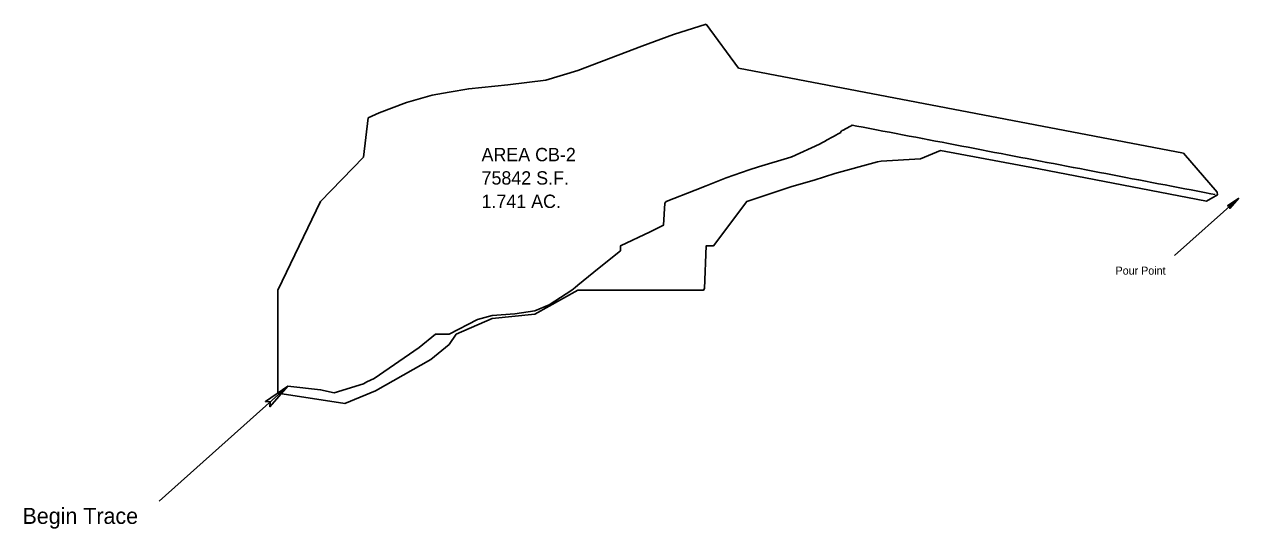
# Model space of a CAD drawing. Extents: x 2048 to 2957, y 2919 to 3297.
import ezdxf

# ---------------------------------------------------------------- set-up
doc = ezdxf.new("R2010")
doc.units = 0
for name, color, linetype in [('Default', 7, 'Continuous'), ('DESIGN - SCRATCH - User 1', 7, 'Continuous'), ('SURVEY - CENTERLINE - Preliminary', 7, 'Continuous'), ('SURVEY - CENTERLINE - Preliminary Text', 7, 'Continuous'), ('SURVEY - DRAINAGE - Area Shapes', 7, 'Continuous')]:
    doc.layers.add(name, color=color, linetype=linetype)

msp = doc.modelspace()

# ---------------------------------------------------------------- linework, layer by layer
at = {"layer": 'DESIGN - SCRATCH - User 1'}
msp.add_line((2957.46, 3167.04), (2909.3, 3124.03), dxfattribs=at)
msp.add_lwpolyline([(2957.46, 3167.04), (2950.79, 3159.41), (2950.93, 3161.21), (2949.09, 3161.31)], close=True, dxfattribs=at)
msp.add_lwpolyline([(2957.46, 3167.04), (2950.79, 3159.41), (2950.93, 3161.21), (2949.09, 3161.31), (2957.46, 3167.04)], dxfattribs=at)
at = {"layer": 'SURVEY - CENTERLINE - Preliminary'}
msp.add_lwpolyline([(2245.41, 3026.11), (2270.08, 3023.51), (2280.28, 3021.33), (2302.16, 3027.91), (2304.59, 3029.37), (2310.25, 3031.88), (2343.85, 3055.13), (2356.11, 3065.07), (2366.31, 3065.07), (2387.56, 3076.27), (2398.39, 3079.13), (2415.55, 3080.5), (2430.47, 3082.64), (2441.22, 3087.13), (2458.22, 3098.26), (2460.61, 3100.25), (2462.54, 3101.8), (2478.58, 3114.85), (2494.62, 3127.7), (2494.62, 3131.44), (2516.69, 3141.79), (2526.7, 3146.81), (2527.9, 3163.39), (2528.85, 3164.63), (2550.54, 3173.15), (2558.77, 3176.37), (2573.78, 3182.29), (2590.85, 3188.26), (2597.81, 3190.62), (2622.2, 3197.82), (2622.7, 3198.04), (2622.71, 3198.05), (2622.84, 3198.11), (2622.91, 3198.14), (2622.93, 3198.15), (2622.97, 3198.17), (2643.58, 3207.65), (2644.49, 3208.07), (2644.64, 3208.13), (2644.9, 3208.27), (2645.24, 3208.44), (2645.87, 3208.77), (2647.37, 3209.61), (2649.3, 3210.68), (2653.05, 3212.79), (2655.01, 3213.88), (2655.37, 3214.08), (2658.03, 3215.55), (2659.55, 3216.35), (2659.55, 3216.35), (2659.55, 3216.35), (2659.59, 3216.51), (2659.78, 3217.29), (2659.95, 3217.38), (2660.64, 3217.74), (2661.2, 3218.03), (2666.3, 3220.7), (2666.91, 3221.02), (2667.61, 3221.39), (2667.89, 3221.7), (2667.99, 3221.82), (2667.99, 3221.82), (2667.99, 3221.82), (2671.48, 3221.16), (2676.39, 3220.22), (2681.3, 3219.28), (2686.21, 3218.34), (2691.12, 3217.4), (2696.03, 3216.46), (2700.94, 3215.52), (2705.85, 3214.58), (2710.76, 3213.64), (2715.67, 3212.7), (2720.58, 3211.76), (2725.5, 3210.82), (2730.41, 3209.88), (2735.32, 3208.94), (2740.23, 3208), (2745.14, 3207.06), (2750.05, 3206.12), (2754.96, 3205.18), (2759.87, 3204.24), (2764.78, 3203.3), (2769.69, 3202.36), (2774.6, 3201.42), (2779.52, 3200.48), (2784.43, 3199.54), (2789.34, 3198.6), (2794.25, 3197.66), (2799.16, 3196.72), (2804.07, 3195.79), (2808.98, 3194.84), (2813.89, 3193.91), (2818.8, 3192.97), (2823.71, 3192.03), (2828.62, 3191.09), (2833.54, 3190.15), (2838.45, 3189.21), (2843.36, 3188.27), (2848.27, 3187.33), (2853.18, 3186.39), (2858.09, 3185.45), (2863, 3184.51), (2867.91, 3183.57), (2872.82, 3182.63), (2877.73, 3181.69), (2882.64, 3180.75), (2887.56, 3179.81), (2892.47, 3178.87), (2897.38, 3177.93), (2902.29, 3176.99), (2907.2, 3176.05), (2912.11, 3175.11), (2917.02, 3174.17), (2921.93, 3173.23), (2926.84, 3172.29), (2931.75, 3171.35), (2936.66, 3170.41), (2939.9, 3169.79)], dxfattribs=at)
at = {"layer": 'SURVEY - CENTERLINE - Preliminary Text'}
msp.add_line((2245.41, 3026.11), (2149.11, 2940.1), dxfattribs=at)
msp.add_lwpolyline([(2245.41, 3026.11), (2232.09, 3010.86), (2232.36, 3014.46), (2228.69, 3014.66)], close=True, dxfattribs=at)
msp.add_lwpolyline([(2245.41, 3026.11), (2232.09, 3010.86), (2232.36, 3014.46), (2228.69, 3014.66), (2245.41, 3026.11)], dxfattribs=at)
at = {"layer": 'SURVEY - DRAINAGE - Area Shapes'}
for p, q in [((2558.77, 3297.38), (2583.06, 3264.55)), ((2583.06, 3264.55), (2916.24, 3200.79)), ((2933.36, 3164.93), (2807.85, 3188.95))]:
    msp.add_line(p, q, dxfattribs=at)
for points in [[(2305.68, 3227.37), (2313.86, 3231.01), (2334.24, 3238.75), (2353.54, 3244.23), (2366.31, 3246.61), (2380.92, 3249.08), (2410.24, 3251.93), (2438.79, 3255.58), (2462.54, 3262.7), (2510.53, 3280.92), (2534.22, 3289.6), (2558.77, 3297.38)], [(2529.54, 3098.26), (2462.54, 3098.26), (2430.47, 3080.21), (2398.39, 3076.83), (2371.56, 3065.07), (2366.31, 3057.45), (2352.46, 3046.21), (2311.04, 3022.69), (2288.19, 3013.15), (2238, 3021.05), (2238, 3098.26), (2270.08, 3164.63), (2302.16, 3197.82), (2305.68, 3227.37)], [(2807.85, 3188.95), (2734.14, 3202.79), (2719.16, 3196.62), (2689.87, 3194.93), (2687.08, 3194.37), (2655.01, 3185.45)], [(2916.24, 3200.79), (2941.37, 3171.55), (2941.57, 3169.47), (2933.36, 3164.93)], [(2655.01, 3185.45), (2639.57, 3180.6), (2622.93, 3175.83), (2589.08, 3164.63), (2564.25, 3131.44), (2558.77, 3131.44), (2557.54, 3099.53), (2556.8, 3098.26), (2529.54, 3098.26)]]:
    msp.add_lwpolyline(points, dxfattribs=at)

# ---------------------------------------------------------------- texts
at = {"layer": 'Default'}
for s, p in [('AREA CB-2', (2390.54, 3194.75)), ('75842 S.F.', (2390.54, 3177.25)), ('1.741 AC.', (2390.54, 3159.75))]:
    msp.add_text(s, height=10, dxfattribs=at).set_placement(p)
at = {"layer": 'DESIGN - SCRATCH - User 1'}
msp.add_text('Pour Point', height=6, dxfattribs=at).set_placement((2865.24, 3109.81))
at = {"layer": 'SURVEY - CENTERLINE - Preliminary Text'}
msp.add_text('Begin Trace', height=12, dxfattribs=at).set_placement((2046.87, 2923.03))

doc.saveas('drawing.dxf')
